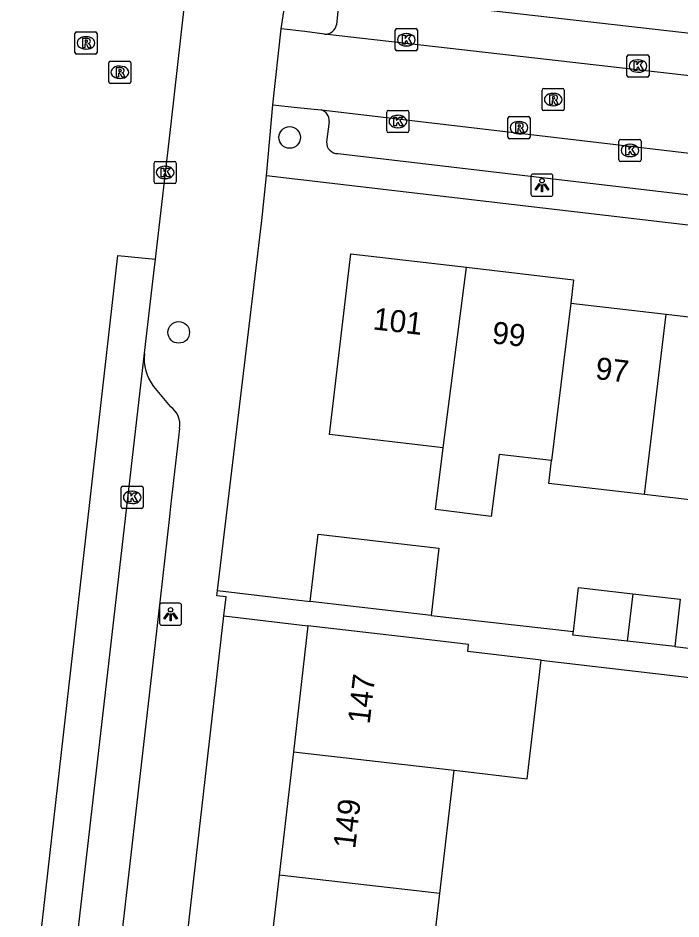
# Model space of a CAD drawing. Extents: x 162250 to 162654, y 380744 to 381605.
# Drawn here: x 162271.15 to 162301.09, y 380930.93 to 380971.62 of the extents above; entities that cross this region are included whole.
import ezdxf

# ---------------------------------------------------------------- set-up
doc = ezdxf.new("R2010")
doc.units = 0
for name, color, linetype in [('IMGEO_Boom', 7, 'Continuous'), ('IMGEO_Kolk', 7, 'Continuous'), ('IMGEO_Lichtpunt', 7, 'Continuous'), ('IMGEO_Pand', 7, 'Continuous'), ('IMGEO_Pand_nummerreeks', 7, 'Continuous'), ('IMGEO_Rijbaan_lokaal_gesloten', 7, 'Continuous'), ('IMGEO_Rijbaan_lokaal_open', 7, 'Continuous'), ('IMGEO_Rioolput', 7, 'Continuous'), ('IMGEO_Voetpad_open', 7, 'Continuous')]:
    doc.layers.add(name, color=color, linetype=linetype)

msp = doc.modelspace()

# ---------------------------------------------------------------- linework, layer by layer
at = {"layer": 'IMGEO_Boom'}
for centre in [(162283.418, 380966.226), (162278.407, 380957.423)]:
    msp.add_circle(centre, 0.489, dxfattribs=at)
at = {"layer": 'IMGEO_Kolk'}
for p, q in [((162288.263, 380971.141), (162289.115, 380971.141)), ((162288.188, 380970.215), (162288.188, 380971.067)), ((162288.676, 380970.921), (162288.701, 380970.921)), ((162289.189, 380971.067), (162289.189, 380970.215)), ((162288.699, 380970.361), (162288.674, 380970.361)), ((162289.115, 380970.141), (162288.263, 380970.141)), ((162298.65, 380969.027), (162298.65, 380969.879)), ((162298.725, 380969.953), (162299.577, 380969.953)), ((162299.651, 380969.879), (162299.651, 380969.027)), ((162299.138, 380969.733), (162299.163, 380969.733)), ((162299.161, 380969.173), (162299.136, 380969.173)), ((162299.577, 380968.953), (162298.725, 380968.953)), ((162287.88, 380967.446), (162288.732, 380967.446)), ((162287.805, 380966.52), (162287.805, 380967.372)), ((162288.293, 380967.226), (162288.318, 380967.226)), ((162288.806, 380967.372), (162288.806, 380966.52)), ((162288.316, 380966.666), (162288.291, 380966.666)), ((162288.732, 380966.446), (162287.88, 380966.446)), ((162298.287, 380965.214), (162298.287, 380966.066)), ((162298.362, 380966.14), (162299.214, 380966.14)), ((162298.775, 380965.92), (162298.8, 380965.92)), ((162299.288, 380966.066), (162299.288, 380965.214)), ((162277.294, 380964.22), (162277.294, 380965.072)), ((162277.369, 380965.146), (162278.221, 380965.146)), ((162278.295, 380965.072), (162278.295, 380964.22)), ((162299.214, 380965.14), (162298.362, 380965.14)), ((162298.798, 380965.36), (162298.773, 380965.36)), ((162277.782, 380964.926), (162277.807, 380964.926)), ((162277.805, 380964.366), (162277.78, 380964.366)), ((162278.221, 380964.146), (162277.369, 380964.146)), ((162275.806, 380949.545), (162275.806, 380950.397)), ((162275.881, 380950.471), (162276.733, 380950.471)), ((162276.807, 380950.397), (162276.807, 380949.545)), ((162276.294, 380950.251), (162276.319, 380950.251)), ((162276.317, 380949.691), (162276.292, 380949.691)), ((162276.733, 380949.471), (162275.881, 380949.471))]:
    msp.add_line(p, q, dxfattribs=at)
for points in [[(162288.263, 380971.141), (162289.115, 380971.141)], [(162288.188, 380970.215), (162288.188, 380971.067)], [(162288.509, 380970.841), (162288.632, 380970.841), (162288.632, 380970.69), (162288.762, 380970.841), (162288.926, 380970.841), (162288.78, 380970.69), (162288.933, 380970.441), (162288.781, 380970.441), (162288.696, 380970.605), (162288.632, 380970.538), (162288.632, 380970.441), (162288.509, 380970.441), (162288.509, 380970.841)], [(162289.189, 380971.067), (162289.189, 380970.215)], [(162289.115, 380970.141), (162288.263, 380970.141)], [(162298.65, 380969.027), (162298.65, 380969.879)], [(162298.725, 380969.953), (162299.577, 380969.953)], [(162299.651, 380969.879), (162299.651, 380969.027)], [(162298.971, 380969.653), (162299.094, 380969.653), (162299.094, 380969.502), (162299.224, 380969.653), (162299.388, 380969.653), (162299.242, 380969.502), (162299.395, 380969.253), (162299.243, 380969.253), (162299.158, 380969.417), (162299.094, 380969.35), (162299.094, 380969.253), (162298.971, 380969.253), (162298.971, 380969.653)], [(162299.577, 380968.953), (162298.725, 380968.953)], [(162287.88, 380967.446), (162288.732, 380967.446)], [(162287.805, 380966.52), (162287.805, 380967.372)], [(162288.126, 380967.146), (162288.249, 380967.146), (162288.249, 380966.995), (162288.379, 380967.146), (162288.543, 380967.146), (162288.397, 380966.995), (162288.55, 380966.746), (162288.398, 380966.746), (162288.313, 380966.91), (162288.249, 380966.843), (162288.249, 380966.746), (162288.126, 380966.746), (162288.126, 380967.146)], [(162288.806, 380967.372), (162288.806, 380966.52)], [(162288.732, 380966.446), (162287.88, 380966.446)], [(162298.287, 380965.214), (162298.287, 380966.066)], [(162298.362, 380966.14), (162299.214, 380966.14)], [(162298.608, 380965.84), (162298.731, 380965.84), (162298.731, 380965.689), (162298.861, 380965.84), (162299.025, 380965.84), (162298.879, 380965.689), (162299.032, 380965.44), (162298.88, 380965.44), (162298.795, 380965.604), (162298.731, 380965.537), (162298.731, 380965.44), (162298.608, 380965.44), (162298.608, 380965.84)], [(162299.288, 380966.066), (162299.288, 380965.214)], [(162277.294, 380964.22), (162277.294, 380965.072)], [(162277.369, 380965.146), (162278.221, 380965.146)], [(162278.295, 380965.072), (162278.295, 380964.22)], [(162299.214, 380965.14), (162298.362, 380965.14)], [(162277.615, 380964.846), (162277.738, 380964.846), (162277.738, 380964.695), (162277.868, 380964.846), (162278.032, 380964.846), (162277.886, 380964.695), (162278.039, 380964.446), (162277.887, 380964.446), (162277.802, 380964.61), (162277.738, 380964.543), (162277.738, 380964.446), (162277.615, 380964.446), (162277.615, 380964.846)], [(162278.221, 380964.146), (162277.369, 380964.146)], [(162275.806, 380949.545), (162275.806, 380950.397)], [(162275.881, 380950.471), (162276.733, 380950.471)], [(162276.807, 380950.397), (162276.807, 380949.545)], [(162276.127, 380950.171), (162276.25, 380950.171), (162276.25, 380950.02), (162276.38, 380950.171), (162276.544, 380950.171), (162276.398, 380950.02), (162276.551, 380949.771), (162276.399, 380949.771), (162276.314, 380949.935), (162276.25, 380949.868), (162276.25, 380949.771), (162276.127, 380949.771), (162276.127, 380950.171)], [(162276.733, 380949.471), (162275.881, 380949.471)]]:
    msp.add_lwpolyline(points, dxfattribs=at)
for centre, start, end in [((162288.265, 380971.065), 91.552, 178.448), ((162288.265, 380971.065), 91.552, 178.448), ((162289.113, 380971.065), 1.552, 88.448), ((162289.113, 380971.065), 1.552, 88.448), ((162288.265, 380970.217), 181.552, 268.448), ((162288.265, 380970.217), 181.552, 268.448), ((162289.113, 380970.217), 271.552, 358.448), ((162289.113, 380970.217), 271.552, 358.448), ((162298.727, 380969.877), 91.552, 178.448), ((162298.727, 380969.877), 91.552, 178.448), ((162299.575, 380969.877), 1.552, 88.448), ((162299.575, 380969.877), 1.552, 88.448), ((162298.727, 380969.029), 181.552, 268.448), ((162298.727, 380969.029), 181.552, 268.448), ((162299.575, 380969.029), 271.552, 358.448), ((162299.575, 380969.029), 271.552, 358.448), ((162287.882, 380967.37), 91.552, 178.448), ((162287.882, 380967.37), 91.552, 178.448), ((162288.73, 380967.37), 1.552, 88.448), ((162288.73, 380967.37), 1.552, 88.448), ((162287.882, 380966.522), 181.552, 268.448), ((162287.882, 380966.522), 181.552, 268.448), ((162288.73, 380966.522), 271.552, 358.448), ((162288.73, 380966.522), 271.552, 358.448), ((162298.364, 380966.064), 91.552, 178.448), ((162298.364, 380966.064), 91.552, 178.448), ((162299.212, 380966.064), 1.552, 88.448), ((162299.212, 380966.064), 1.552, 88.448), ((162277.371, 380965.07), 91.552, 178.448), ((162277.371, 380965.07), 91.552, 178.448), ((162278.219, 380965.07), 1.552, 88.448), ((162278.219, 380965.07), 1.552, 88.448), ((162298.364, 380965.216), 181.552, 268.448), ((162298.364, 380965.216), 181.552, 268.448), ((162299.212, 380965.216), 271.552, 358.448), ((162299.212, 380965.216), 271.552, 358.448), ((162277.371, 380964.222), 181.552, 268.448), ((162277.371, 380964.222), 181.552, 268.448), ((162278.219, 380964.222), 271.552, 358.448), ((162278.219, 380964.222), 271.552, 358.448), ((162275.883, 380950.395), 91.552, 178.448), ((162275.883, 380950.395), 91.552, 178.448), ((162276.731, 380950.395), 1.552, 88.448), ((162276.731, 380950.395), 1.552, 88.448), ((162275.883, 380949.547), 181.552, 268.448), ((162275.883, 380949.547), 181.552, 268.448), ((162276.731, 380949.547), 271.552, 358.448), ((162276.731, 380949.547), 271.552, 358.448)]:
    msp.add_arc(centre, 0.0765, start, end, dxfattribs=at)
for centre, major_axis, ratio, start_param, end_param in [((162288.675, 380970.641), (-0.387, 0.002), 0.722429, 4.712389, 7.853982), ((162288.7, 380970.641), (-0.39, 0.002), 0.717154, 1.570796, 4.712389), ((162299.137, 380969.453), (-0.387, 0.002), 0.722429, 4.712389, 7.853982), ((162299.162, 380969.453), (-0.39, 0.002), 0.717154, 1.570796, 4.712389), ((162288.292, 380966.946), (-0.387, 0.002), 0.722429, 4.712389, 7.853982), ((162288.317, 380966.946), (-0.39, 0.002), 0.717154, 1.570796, 4.712389), ((162298.774, 380965.64), (-0.387, 0.002), 0.722429, 4.712389, 7.853982), ((162298.799, 380965.64), (-0.39, 0.002), 0.717154, 1.570796, 4.712389), ((162277.781, 380964.646), (-0.387, 0.002), 0.722429, 4.712389, 7.853982), ((162277.806, 380964.646), (-0.39, 0.002), 0.717154, 1.570796, 4.712389), ((162276.293, 380949.971), (-0.387, 0.002), 0.722429, 4.712389, 7.853982), ((162276.318, 380949.971), (-0.39, 0.002), 0.717154, 1.570796, 4.712389)]:
    msp.add_ellipse(centre, major_axis=major_axis, ratio=ratio, start_param=start_param, end_param=end_param, dxfattribs=at)
at = {"layer": 'IMGEO_Lichtpunt'}
for p, q in [((162294.315, 380964.476), (162294.315, 380963.669)), ((162294.315, 380964.476), (162294.315, 380963.669)), ((162295.217, 380964.571), (162294.409, 380964.571)), ((162295.217, 380964.571), (162294.409, 380964.571)), ((162295.311, 380963.669), (162295.311, 380964.476)), ((162295.311, 380963.669), (162295.311, 380964.476)), ((162294.409, 380963.575), (162295.217, 380963.575)), ((162294.409, 380963.575), (162295.217, 380963.575)), ((162277.541, 380945.095), (162277.541, 380944.288)), ((162277.541, 380945.095), (162277.541, 380944.288)), ((162278.443, 380945.19), (162277.635, 380945.19)), ((162278.443, 380945.19), (162277.635, 380945.19)), ((162278.537, 380944.288), (162278.537, 380945.095)), ((162278.537, 380944.288), (162278.537, 380945.095)), ((162277.635, 380944.194), (162278.443, 380944.194)), ((162277.635, 380944.194), (162278.443, 380944.194))]:
    msp.add_line(p, q, dxfattribs=at)
for points in [[(162294.689, 380964.14), (162294.728, 380964.112), (162294.54, 380963.85), (162294.502, 380963.877), (162294.689, 380964.14)], [(162294.791, 380964.092), (162294.838, 380964.092), (162294.838, 380963.77), (162294.791, 380963.77), (162294.791, 380964.092)], [(162294.901, 380964.112), (162294.939, 380964.139), (162295.126, 380963.877), (162295.087, 380963.849), (162294.901, 380964.112)], [(162277.915, 380944.759), (162277.954, 380944.731), (162277.766, 380944.469), (162277.728, 380944.496), (162277.915, 380944.759)], [(162278.017, 380944.711), (162278.064, 380944.711), (162278.064, 380944.389), (162278.017, 380944.389), (162278.017, 380944.711)], [(162278.127, 380944.731), (162278.165, 380944.758), (162278.352, 380944.496), (162278.313, 380944.468), (162278.127, 380944.731)]]:
    msp.add_lwpolyline(points, dxfattribs=at)
for centre in [(162294.814, 380964.274), (162278.04, 380944.893)]:
    msp.add_circle(centre, 0.0994, dxfattribs=at)
for centre, start, end in [((162294.409, 380964.476), 90, 180), ((162294.409, 380964.476), 90, 180), ((162295.217, 380964.476), 0, 90), ((162295.217, 380964.476), 0, 90), ((162294.409, 380963.669), 180, 270), ((162294.409, 380963.669), 180, 270), ((162295.217, 380963.669), 270, 0), ((162295.217, 380963.669), 270, 360), ((162277.635, 380945.095), 90, 180), ((162277.635, 380945.095), 90, 180), ((162278.443, 380945.095), 0, 90), ((162278.443, 380945.095), 0, 90), ((162277.635, 380944.288), 180, 270), ((162277.635, 380944.288), 180, 270), ((162278.443, 380944.288), 270, 0), ((162278.443, 380944.288), 270, 360)]:
    msp.add_arc(centre, 0.0946, start, end, dxfattribs=at)
at = {"layer": 'IMGEO_Pand'}
for points in [[(162290.355, 380952.205), (162285.219, 380952.805), (162286.174, 380960.976), (162291.402, 380960.365)], [(162290.355, 380952.205), (162291.402, 380960.365)], [(162291.402, 380960.365), (162296.244, 380959.8), (162296.121, 380958.748)], [(162296.121, 380958.748), (162295.249, 380951.633)], [(162296.121, 380958.748), (162300.42, 380958.246)], [(162299.446, 380950.096), (162300.42, 380958.246)], [(162300.42, 380958.246), (162305.005, 380957.71)], [(162295.249, 380951.633), (162292.884, 380951.909), (162292.524, 380949.103), (162289.999, 380949.427), (162290.355, 380952.205)], [(162299.446, 380950.096), (162295.128, 380950.601), (162295.249, 380951.633)], [(162304.032, 380949.56), (162299.446, 380950.096)], [(162284.351, 380945.265), (162284.704, 380948.314), (162290.159, 380947.682), (162289.806, 380944.633)], [(162296.232, 380943.907), (162296.457, 380945.895), (162298.911, 380945.617)], [(162298.911, 380945.617), (162298.655, 380943.477)], [(162298.911, 380945.617), (162301.062, 380945.374), (162300.819, 380943.232)], [(162289.806, 380944.633), (162284.351, 380945.265)], [(162284.245, 380944.173), (162283.585, 380938.484)], [(162294.77, 380942.618), (162291.463, 380943.002), (162291.501, 380943.332), (162289.205, 380943.598), (162284.245, 380944.173)], [(162298.655, 380943.477), (162296.215, 380943.753), (162296.232, 380943.907)], [(162300.819, 380943.232), (162298.655, 380943.477)], [(162290.841, 380937.645), (162294.148, 380937.263), (162294.77, 380942.618)], [(162283.585, 380938.484), (162282.938, 380932.912)], [(162283.585, 380938.484), (162290.841, 380937.645)], [(162290.195, 380932.072), (162290.841, 380937.645)], [(162282.938, 380932.912), (162282.292, 380927.341)], [(162290.195, 380932.072), (162282.938, 380932.912)], [(162289.549, 380926.502), (162290.195, 380932.072)]]:
    msp.add_lwpolyline(points, dxfattribs=at)
at = {"layer": 'IMGEO_Rijbaan_lokaal_gesloten'}
for points in [[(162277.356, 380960.724), (162278.069, 380966.836), (162278.655, 380972.068), (162279.19, 380976.722), (162279.196, 380976.775), (162279.203, 380976.84)], [(162271.149, 380921.172), (162275.659, 380960.888), (162277.356, 380960.724)], [(162276.86, 380956.476), (162277.285, 380960.114), (162277.356, 380960.724)], [(162272.782, 380920.985), (162276.86, 380956.476)]]:
    msp.add_lwpolyline(points, dxfattribs=at)
at = {"layer": 'IMGEO_Rijbaan_lokaal_open'}
for points in [[(162282.665, 380967.703), (162283.032, 380971.129)], [(162284.995, 380970.888), (162284.107, 380971.014), (162283.032, 380971.129)], [(162332.355, 380965.483), (162284.995, 380970.888)], [(162282.665, 380967.703), (162283.759, 380967.586), (162284.836, 380967.471)], [(162284.836, 380967.471), (162330.529, 380962.093)]]:
    msp.add_lwpolyline(points, dxfattribs=at)
at = {"layer": 'IMGEO_Rioolput'}
for p, q in [((162273.72, 380970.069), (162273.72, 380970.921)), ((162273.795, 380970.995), (162274.647, 380970.995)), ((162274.208, 380970.775), (162274.233, 380970.775)), ((162274.721, 380970.921), (162274.721, 380970.069)), ((162274.647, 380969.995), (162273.795, 380969.995)), ((162274.231, 380970.215), (162274.206, 380970.215)), ((162275.245, 380968.743), (162275.245, 380969.595)), ((162275.32, 380969.669), (162276.172, 380969.669)), ((162276.246, 380969.595), (162276.246, 380968.743)), ((162275.733, 380969.449), (162275.758, 380969.449)), ((162276.172, 380968.669), (162275.32, 380968.669)), ((162275.756, 380968.889), (162275.731, 380968.889)), ((162294.821, 380967.511), (162294.821, 380968.363)), ((162294.896, 380968.437), (162295.748, 380968.437)), ((162295.822, 380968.363), (162295.822, 380967.511)), ((162295.309, 380968.217), (162295.334, 380968.217)), ((162295.748, 380967.437), (162294.896, 380967.437)), ((162295.332, 380967.657), (162295.307, 380967.657)), ((162293.274, 380966.242), (162293.274, 380967.094)), ((162293.349, 380967.168), (162294.201, 380967.168)), ((162294.275, 380967.094), (162294.275, 380966.242)), ((162293.762, 380966.948), (162293.787, 380966.948)), ((162293.785, 380966.388), (162293.76, 380966.388)), ((162294.201, 380966.168), (162293.349, 380966.168))]:
    msp.add_line(p, q, dxfattribs=at)
for points in [[(162273.72, 380970.069), (162273.72, 380970.921)], [(162273.795, 380970.995), (162274.647, 380970.995)], [(162274.309, 380970.693), (162274.057, 380970.695), (162274.057, 380970.295)], [(162274.721, 380970.921), (162274.721, 380970.069)], [(162274.057, 380970.295), (162274.181, 380970.295), (162274.181, 380970.457), (162274.192, 380970.457)], [(162274.235, 380970.614), (162274.181, 380970.614), (162274.181, 380970.533)], [(162274.181, 380970.533), (162274.233, 380970.533)], [(162274.239, 380970.428), (162274.31, 380970.295), (162274.45, 380970.295), (162274.385, 380970.421)], [(162274.647, 380969.995), (162273.795, 380969.995)], [(162275.245, 380968.743), (162275.245, 380969.595)], [(162275.32, 380969.669), (162276.172, 380969.669)], [(162276.246, 380969.595), (162276.246, 380968.743)], [(162275.834, 380969.367), (162275.582, 380969.369), (162275.582, 380968.969)], [(162275.582, 380968.969), (162275.706, 380968.969), (162275.706, 380969.131), (162275.717, 380969.131)], [(162275.76, 380969.288), (162275.706, 380969.288), (162275.706, 380969.207)], [(162275.706, 380969.207), (162275.758, 380969.207)], [(162275.764, 380969.102), (162275.835, 380968.969), (162275.975, 380968.969), (162275.91, 380969.095)], [(162276.172, 380968.669), (162275.32, 380968.669)], [(162294.821, 380967.511), (162294.821, 380968.363)], [(162294.896, 380968.437), (162295.748, 380968.437)], [(162295.822, 380968.363), (162295.822, 380967.511)], [(162295.41, 380968.135), (162295.158, 380968.137), (162295.158, 380967.737)], [(162295.158, 380967.737), (162295.282, 380967.737), (162295.282, 380967.899), (162295.293, 380967.899)], [(162295.336, 380968.056), (162295.282, 380968.056), (162295.282, 380967.975)], [(162295.282, 380967.975), (162295.334, 380967.975)], [(162295.34, 380967.87), (162295.411, 380967.737), (162295.551, 380967.737), (162295.486, 380967.863)], [(162295.748, 380967.437), (162294.896, 380967.437)], [(162293.274, 380966.242), (162293.274, 380967.094)], [(162293.349, 380967.168), (162294.201, 380967.168)], [(162294.275, 380967.094), (162294.275, 380966.242)], [(162293.863, 380966.866), (162293.611, 380966.868), (162293.611, 380966.468)], [(162293.611, 380966.468), (162293.735, 380966.468), (162293.735, 380966.63), (162293.746, 380966.63)], [(162293.789, 380966.787), (162293.735, 380966.787), (162293.735, 380966.706)], [(162293.735, 380966.706), (162293.787, 380966.706)], [(162293.793, 380966.601), (162293.864, 380966.468), (162294.004, 380966.468), (162293.939, 380966.594)], [(162294.201, 380966.168), (162293.349, 380966.168)]]:
    msp.add_lwpolyline(points, dxfattribs=at)
for centre, radius, start, end in [((162273.797, 380970.919), 0.0765, 91.552, 178.448), ((162273.797, 380970.919), 0.0765, 91.552, 178.448), ((162274.308, 380970.583), 0.109, 350.3612, 89.416), ((162274.645, 380970.919), 0.0765, 1.552, 88.448), ((162274.645, 380970.919), 0.0765, 1.552, 88.448), ((162274.191, 380970.404), 0.0533, 26.0293, 88.6989), ((162274.217, 380970.722), 0.19, 274.7715, 282.9687), ((162274.241, 380970.518), 0.0964, 77.0061, 93.1865), ((162274.255, 380970.575), 0.0378, 276.6634, 79.6772), ((162274.306, 380970.583), 0.112, 277.5842, 350.9817), ((162274.29, 380970.368), 0.108, 29.5134, 73.7905), ((162273.797, 380970.071), 0.0765, 181.552, 268.448), ((162273.797, 380970.071), 0.0765, 181.552, 268.448), ((162274.645, 380970.071), 0.0765, 271.552, 358.448), ((162274.645, 380970.071), 0.0765, 271.552, 358.448), ((162275.322, 380969.593), 0.0765, 91.552, 178.448), ((162275.322, 380969.593), 0.0765, 91.552, 178.448), ((162276.17, 380969.593), 0.0765, 1.552, 88.448), ((162276.17, 380969.593), 0.0765, 1.552, 88.448), ((162275.716, 380969.078), 0.0533, 26.0293, 88.6989), ((162275.742, 380969.396), 0.19, 274.7715, 282.9687), ((162275.766, 380969.192), 0.0964, 77.0061, 93.1865), ((162275.78, 380969.249), 0.0378, 276.6634, 79.6772), ((162275.833, 380969.257), 0.109, 350.3612, 89.416), ((162275.831, 380969.257), 0.112, 277.5842, 350.9817), ((162275.815, 380969.042), 0.108, 29.5134, 73.7905), ((162275.322, 380968.745), 0.0765, 181.552, 268.448), ((162275.322, 380968.745), 0.0765, 181.552, 268.448), ((162276.17, 380968.745), 0.0765, 271.552, 358.448), ((162276.17, 380968.745), 0.0765, 271.552, 358.448), ((162294.898, 380968.361), 0.0765, 91.552, 178.448), ((162294.898, 380968.361), 0.0765, 91.552, 178.448), ((162295.746, 380968.361), 0.0765, 1.552, 88.448), ((162295.746, 380968.361), 0.0765, 1.552, 88.448), ((162295.292, 380967.846), 0.0533, 26.0293, 88.6989), ((162295.318, 380968.164), 0.19, 274.7715, 282.9687), ((162295.342, 380967.96), 0.0964, 77.0061, 93.1865), ((162295.356, 380968.017), 0.0378, 276.6634, 79.6772), ((162295.409, 380968.025), 0.109, 350.3612, 89.416), ((162295.407, 380968.025), 0.112, 277.5842, 350.9817), ((162295.391, 380967.81), 0.108, 29.5134, 73.7905), ((162294.898, 380967.513), 0.0765, 181.552, 268.448), ((162294.898, 380967.513), 0.0765, 181.552, 268.448), ((162295.746, 380967.513), 0.0765, 271.552, 358.448), ((162295.746, 380967.513), 0.0765, 271.552, 358.448), ((162293.351, 380967.092), 0.0765, 91.552, 178.448), ((162293.351, 380967.092), 0.0765, 91.552, 178.448), ((162294.199, 380967.092), 0.0765, 1.552, 88.448), ((162294.199, 380967.092), 0.0765, 1.552, 88.448), ((162293.745, 380966.577), 0.0533, 26.0293, 88.6989), ((162293.771, 380966.895), 0.19, 274.7715, 282.9687), ((162293.795, 380966.691), 0.0964, 77.0061, 93.1865), ((162293.809, 380966.748), 0.0378, 276.6634, 79.6772), ((162293.862, 380966.756), 0.109, 350.3612, 89.416), ((162293.86, 380966.756), 0.112, 277.5842, 350.9817), ((162293.844, 380966.541), 0.108, 29.5134, 73.7905), ((162293.351, 380966.244), 0.0765, 181.552, 268.448), ((162293.351, 380966.244), 0.0765, 181.552, 268.448), ((162294.199, 380966.244), 0.0765, 271.552, 358.448), ((162294.199, 380966.244), 0.0765, 271.552, 358.448)]:
    msp.add_arc(centre, radius, start, end, dxfattribs=at)
for centre, major_axis, ratio, start_param, end_param in [((162274.207, 380970.495), (-0.387, 0.002), 0.722429, 4.712389, 7.853982), ((162274.232, 380970.495), (-0.39, 0.002), 0.717154, 1.570796, 4.712389), ((162275.732, 380969.169), (-0.387, 0.002), 0.722429, 4.712389, 7.853982), ((162275.757, 380969.169), (-0.39, 0.002), 0.717154, 1.570796, 4.712389), ((162295.308, 380967.937), (-0.387, 0.002), 0.722429, 4.712389, 7.853982), ((162295.333, 380967.937), (-0.39, 0.002), 0.717154, 1.570796, 4.712389), ((162293.761, 380966.668), (-0.387, 0.002), 0.722429, 4.712389, 7.853982), ((162293.786, 380966.668), (-0.39, 0.002), 0.717154, 1.570796, 4.712389)]:
    msp.add_ellipse(centre, major_axis=major_axis, ratio=ratio, start_param=start_param, end_param=end_param, dxfattribs=at)
at = {"layer": 'IMGEO_Voetpad_open'}
for points in [[(162283.032, 380971.129), (162283.298, 380972.915), (162283.492, 380974.216)], [(162332.037, 380967.44), (162286.174, 380972.683)], [(162285.631, 380972.233), (162285.538, 380971.317)], [(162282.368, 380964.496), (162282.665, 380967.703)], [(162285.198, 380966.952), (162285.084, 380966.025)], [(162285.595, 380965.499), (162329.39, 380960.351)], [(162280.158, 380945.767), (162282.16, 380962.478), (162282.368, 380964.496)], [(162396.364, 380951.153), (162282.368, 380964.496)], [(162277.27, 380954.984), (162278.017, 380954.074)], [(162278.444, 380953.074), (162278.043, 380949.56), (162277.992, 380949.113), (162277.569, 380945.379), (162277.45, 380944.323), (162274.954, 380922.547)], [(162280.452, 380944.613), (162280.552, 380945.483), (162280.129, 380945.528), (162280.158, 380945.767)], [(162280.158, 380945.767), (162284.351, 380945.265)], [(162277.054, 380914.909), (162280.452, 380944.613)], [(162280.452, 380944.613), (162284.245, 380944.173)], [(162289.806, 380944.633), (162296.232, 380943.907)], [(162300.819, 380943.232), (162305.929, 380942.621)], [(162294.77, 380942.618), (162305.109, 380941.418)]]:
    msp.add_lwpolyline(points, dxfattribs=at)
for centre, radius, start, end in [((162285.009, 380971.428), 0.54, 268.4873, 348.134), ((162284.718, 380967.003), 0.483, 353.9331, 75.8581), ((162285.588, 380966.003), 0.504, 177.5335, 270.809), ((162278.94, 380956.245), 2.093, 173.6741, 217.057), ((162277.51, 380953.267), 0.953, 348.3491, 57.8959)]:
    msp.add_arc(centre, radius, start, end, dxfattribs=at)

# ---------------------------------------------------------------- texts
at = {"layer": 'IMGEO_Pand_nummerreeks'}
for s, rotation, p in [('101', 353.339, (162287.146, 380957.561)), ('99', 353.339, (162292.525, 380956.932)), ('97', 353.307, (162297.195, 380955.32)), ('147', 83.3825, (162287.028, 380939.702)), ('149', 83.3818, (162286.375, 380934.071))]:
    msp.add_text(s, height=1, rotation=rotation, dxfattribs=at).set_placement(p)

doc.saveas('drawing.dxf')
